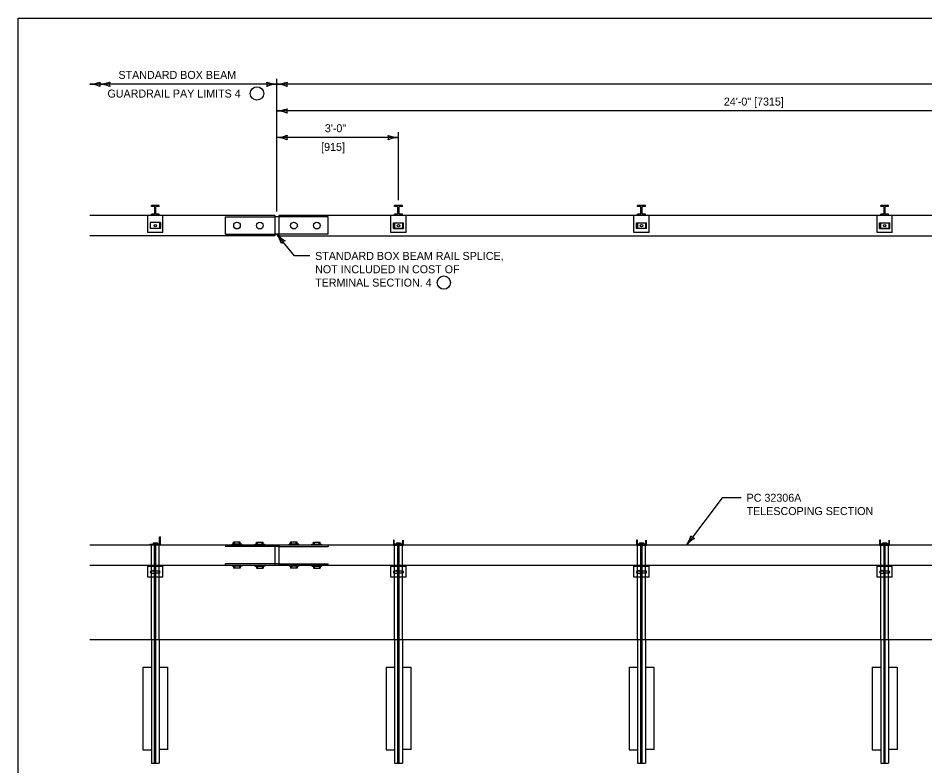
# Model space of a CAD drawing. Extents: x 49991.4 to 50021, y 49987.6 to 50011.4.
# Drawn here: x 49999.38 to 50006.18, y 49993.39 to 49999 of the extents above; entities that cross this region are included whole.
import ezdxf

# ---------------------------------------------------------------- set-up
doc = ezdxf.new("R2010")
doc.units = 0
for name, color, linetype in [('Level 1', 7, 'Continuous'), ('Level 2', 7, 'Continuous'), ('Level 3', 7, 'Continuous'), ('Level 4', 7, 'Continuous')]:
    doc.layers.add(name, color=color, linetype=linetype)

msp = doc.modelspace()

# ---------------------------------------------------------------- linework, layer by layer
at = {"layer": 'Level 1'}
for p, q in [((50000.3826, 49997.5847), (50000.3826, 49997.5939)), ((50000.4416, 49997.5939), (50000.3826, 49997.5939)), ((50000.4075, 49997.5847), (50000.3826, 49997.5847)), ((50000.4075, 49997.5271), (50000.4075, 49997.5847)), ((50000.4167, 49997.5271), (50000.4167, 49997.5847)), ((50000.4416, 49997.5847), (50000.4167, 49997.5847)), ((50000.4416, 49997.5847), (50000.4416, 49997.5939)), ((50002.2056, 49997.5847), (50002.2056, 49997.5939)), ((50002.2647, 49997.5939), (50002.2056, 49997.5939)), ((50002.2306, 49997.5847), (50002.2056, 49997.5847)), ((50002.2306, 49997.5271), (50002.2306, 49997.5847)), ((50002.2397, 49997.5271), (50002.2397, 49997.5847)), ((50002.2647, 49997.5847), (50002.2397, 49997.5847)), ((50002.2647, 49997.5847), (50002.2647, 49997.5939)), ((50004.0288, 49997.5846), (50004.0288, 49997.5938)), ((50004.0879, 49997.5938), (50004.0288, 49997.5938)), ((50004.0539, 49997.5846), (50004.0288, 49997.5846)), ((50004.0539, 49997.527), (50004.0539, 49997.5846)), ((50004.0628, 49997.527), (50004.0628, 49997.5846)), ((50004.0879, 49997.5846), (50004.0628, 49997.5846)), ((50004.0879, 49997.5846), (50004.0879, 49997.5938)), ((50005.8519, 49997.5846), (50005.8519, 49997.5938)), ((50005.911, 49997.5938), (50005.8519, 49997.5938)), ((50005.8769, 49997.5846), (50005.8519, 49997.5846)), ((50005.8769, 49997.527), (50005.8769, 49997.5846)), ((50005.886, 49997.527), (50005.886, 49997.5846)), ((50005.911, 49997.5846), (50005.886, 49997.5846)), ((50005.911, 49997.5846), (50005.911, 49997.5938)), ((50001.3096, 49997.5179), (49999.9212, 49997.5179)), ((50000.4075, 49997.5271), (50000.3826, 49997.5271)), ((50000.3826, 49997.5179), (50000.3826, 49997.5271)), ((50000.4416, 49997.5271), (50000.4167, 49997.5271)), ((50000.4416, 49997.5179), (50000.4416, 49997.5271)), ((50001.3096, 49997.5178), (50001.3096, 49997.366)), ((50001.3379, 49997.5066), (50001.3096, 49997.5066)), ((50001.3379, 49997.5178), (50001.3379, 49997.3659)), ((50008.3123, 49997.5178), (50001.3379, 49997.5178)), ((50002.2306, 49997.5271), (50002.2056, 49997.5271)), ((50002.2056, 49997.5178), (50002.2056, 49997.5271)), ((50002.2647, 49997.5271), (50002.2397, 49997.5271)), ((50002.2647, 49997.5178), (50002.2647, 49997.5271)), ((50004.0539, 49997.527), (50004.0288, 49997.527)), ((50004.0288, 49997.5178), (50004.0288, 49997.527)), ((50004.0879, 49997.527), (50004.0628, 49997.527)), ((50004.0879, 49997.5178), (50004.0879, 49997.527)), ((50005.8769, 49997.527), (50005.8519, 49997.527)), ((50005.8519, 49997.5178), (50005.8519, 49997.527)), ((50005.911, 49997.527), (50005.886, 49997.527)), ((50005.911, 49997.5178), (50005.911, 49997.527)), ((50000.3743, 49997.4642), (50000.3743, 49997.4198)), ((50000.4501, 49997.4642), (50000.3743, 49997.4642)), ((50000.444, 49997.4642), (50000.444, 49997.4198)), ((50000.4501, 49997.4642), (50000.4501, 49997.4198)), ((50002.1978, 49997.4637), (50002.273, 49997.4637)), ((50002.1978, 49997.4203), (50002.1978, 49997.4637)), ((50002.2046, 49997.4637), (50002.2046, 49997.4203)), ((50002.2662, 49997.4637), (50002.2662, 49997.4203)), ((50002.273, 49997.4203), (50002.273, 49997.4637)), ((50002.273, 49997.4203), (50002.273, 49997.4637)), ((50004.0207, 49997.4636), (50004.0959, 49997.4636)), ((50004.0207, 49997.4202), (50004.0207, 49997.4636)), ((50004.0275, 49997.4636), (50004.0275, 49997.4202)), ((50004.0891, 49997.4636), (50004.0891, 49997.4202)), ((50004.0959, 49997.4202), (50004.0959, 49997.4636)), ((50005.8439, 49997.4636), (50005.9192, 49997.4636)), ((50005.8439, 49997.4202), (50005.8439, 49997.4636)), ((50005.8508, 49997.4636), (50005.8508, 49997.4202)), ((50005.9123, 49997.4636), (50005.9123, 49997.4202)), ((50005.9192, 49997.4202), (50005.9192, 49997.4636)), ((50005.9192, 49997.4202), (50005.9192, 49997.4636)), ((50001.3096, 49997.366), (49999.9212, 49997.366)), ((50000.4501, 49997.4198), (50000.3743, 49997.4198)), ((50001.3379, 49997.3771), (50001.3096, 49997.3772)), ((50002.1978, 49997.4203), (50002.273, 49997.4203)), ((50002.273, 49997.4203), (50002.1978, 49997.4203)), ((50004.0959, 49997.4202), (50004.0207, 49997.4202)), ((50005.8439, 49997.4202), (50005.9192, 49997.4202)), ((50005.9192, 49997.4202), (50005.8439, 49997.4202)), ((50008.3121, 49995.0439), (49999.9212, 49995.0439)), ((50000.374, 49995.0439), (50000.374, 49995.0502)), ((50000.374, 49995.0502), (50000.4436, 49995.0502)), ((50000.3964, 49995.0614), (50000.4277, 49995.0614)), ((50000.3964, 49995.0614), (50000.3964, 49995.0502)), ((50000.4033, 49995.0614), (50000.4033, 49995.0502)), ((50000.4211, 49995.0614), (50000.4211, 49995.0502)), ((50000.4277, 49995.0614), (50000.4277, 49995.0502)), ((50000.4436, 49995.1072), (50000.4499, 49995.1072)), ((50000.4436, 49995.0502), (50000.4436, 49995.1072)), ((50000.4499, 49995.0439), (50000.4499, 49995.1072)), ((50001.0599, 49995.0511), (50000.9889, 49995.0511)), ((50000.9889, 49995.044), (50000.9889, 49995.0511)), ((50000.9996, 49995.0511), (50000.9996, 49995.0653)), ((50001.0494, 49995.0653), (50000.9996, 49995.0653)), ((50001.0066, 49995.0511), (50001.0066, 49995.0653)), ((50001.0423, 49995.0511), (50001.0423, 49995.0653)), ((50001.0494, 49995.0511), (50001.0494, 49995.0653)), ((50001.0599, 49995.044), (50001.0599, 49995.0511)), ((50001.1597, 49995.0511), (50001.2308, 49995.0511)), ((50001.1597, 49995.044), (50001.1597, 49995.0511)), ((50001.1704, 49995.0653), (50001.2203, 49995.0653)), ((50001.1704, 49995.0511), (50001.1704, 49995.0653)), ((50001.1775, 49995.0511), (50001.1775, 49995.0653)), ((50001.2132, 49995.0511), (50001.2132, 49995.0653)), ((50001.2203, 49995.0511), (50001.2203, 49995.0653)), ((50001.2308, 49995.044), (50001.2308, 49995.0511)), ((50001.3093, 49995.0439), (50001.3093, 49994.892)), ((50001.3376, 49995.0439), (50001.3376, 49994.892)), ((50001.4873, 49995.0511), (50001.4161, 49995.0511)), ((50001.4161, 49995.044), (50001.4161, 49995.0511)), ((50001.4767, 49995.0653), (50001.4268, 49995.0653)), ((50001.4268, 49995.0511), (50001.4268, 49995.0653)), ((50001.4339, 49995.0511), (50001.4339, 49995.0653)), ((50001.4696, 49995.0511), (50001.4696, 49995.0653)), ((50001.4767, 49995.0511), (50001.4767, 49995.0653)), ((50001.4873, 49995.044), (50001.4873, 49995.0511)), ((50001.5871, 49995.0511), (50001.6582, 49995.0511)), ((50001.5871, 49995.044), (50001.5871, 49995.0511)), ((50001.5977, 49995.0653), (50001.6477, 49995.0653)), ((50001.5977, 49995.0511), (50001.5977, 49995.0653)), ((50001.6048, 49995.0511), (50001.6048, 49995.0653)), ((50001.6405, 49995.0511), (50001.6405, 49995.0653)), ((50001.6477, 49995.0511), (50001.6477, 49995.0653)), ((50001.6582, 49995.044), (50001.6582, 49995.0511)), ((50002.204, 49995.0815), (50002.1971, 49995.0815)), ((50002.1971, 49995.0815), (50002.1971, 49995.0439)), ((50002.1971, 49995.0439), (50002.2724, 49995.0439)), ((50002.204, 49995.0504), (50002.204, 49995.0815)), ((50002.2655, 49995.0504), (50002.204, 49995.0504)), ((50002.2196, 49995.0614), (50002.2509, 49995.0614)), ((50002.2196, 49995.0614), (50002.2196, 49995.0504)), ((50002.2264, 49995.0614), (50002.2264, 49995.0504)), ((50002.2441, 49995.0614), (50002.2441, 49995.0504)), ((50002.2509, 49995.0614), (50002.2509, 49995.0504)), ((50002.2655, 49995.0815), (50002.2655, 49995.0504)), ((50002.2724, 49995.0439), (50002.2724, 49995.0815)), ((50004.0274, 49995.0815), (50004.0205, 49995.0815)), ((50004.0205, 49995.0815), (50004.0205, 49995.0439)), ((50004.0205, 49995.0439), (50004.0958, 49995.0439)), ((50004.0274, 49995.0504), (50004.0274, 49995.0815)), ((50004.0889, 49995.0504), (50004.0274, 49995.0504)), ((50004.0426, 49995.0614), (50004.074, 49995.0614)), ((50004.0426, 49995.0614), (50004.0426, 49995.0504)), ((50004.0495, 49995.0614), (50004.0495, 49995.0504)), ((50004.0673, 49995.0614), (50004.0673, 49995.0504)), ((50004.074, 49995.0614), (50004.074, 49995.0504)), ((50004.0889, 49995.0815), (50004.0889, 49995.0504)), ((50004.0958, 49995.0439), (50004.0958, 49995.0815)), ((50005.8503, 49995.0815), (50005.8435, 49995.0815)), ((50005.8435, 49995.0815), (50005.8435, 49995.0439)), ((50005.8435, 49995.0439), (50005.9187, 49995.0439)), ((50005.8503, 49995.0504), (50005.8503, 49995.0815)), ((50005.9119, 49995.0504), (50005.8503, 49995.0504)), ((50005.8659, 49995.0614), (50005.8972, 49995.0614)), ((50005.8659, 49995.0614), (50005.8659, 49995.0504)), ((50005.8727, 49995.0614), (50005.8727, 49995.0504)), ((50005.8904, 49995.0614), (50005.8904, 49995.0504)), ((50005.8972, 49995.0614), (50005.8972, 49995.0504)), ((50005.9119, 49995.0815), (50005.9119, 49995.0504)), ((50005.9187, 49995.0439), (50005.9187, 49995.0815)), ((50001.3376, 49995.0327), (50001.3093, 49995.0327)), ((50008.3121, 49994.892), (49999.9212, 49994.892)), ((50000.3551, 49994.8034), (50000.3551, 49994.892)), ((50000.469, 49994.8825), (50000.3551, 49994.8825)), ((50000.4415, 49994.8493), (50000.404, 49994.8493)), ((50000.469, 49994.8034), (50000.469, 49994.892)), ((50000.9889, 49994.892), (50000.9889, 49994.8849)), ((50001.0599, 49994.8849), (50000.9889, 49994.8849)), ((50000.9996, 49994.8849), (50000.9996, 49994.8707)), ((50001.0494, 49994.8707), (50000.9996, 49994.8707)), ((50001.0066, 49994.8849), (50001.0066, 49994.8707)), ((50001.0423, 49994.8849), (50001.0423, 49994.8707)), ((50001.0494, 49994.8849), (50001.0494, 49994.8707)), ((50001.0599, 49994.892), (50001.0599, 49994.8849)), ((50001.1597, 49994.892), (50001.1597, 49994.8849)), ((50001.1597, 49994.8849), (50001.2308, 49994.8849)), ((50001.1704, 49994.8849), (50001.1704, 49994.8707)), ((50001.1704, 49994.8707), (50001.2203, 49994.8707)), ((50001.1775, 49994.8849), (50001.1775, 49994.8707)), ((50001.2132, 49994.8849), (50001.2132, 49994.8707)), ((50001.2203, 49994.8849), (50001.2203, 49994.8707)), ((50001.2308, 49994.892), (50001.2308, 49994.8849)), ((50001.3376, 49994.9032), (50001.3093, 49994.9032)), ((50001.4161, 49994.892), (50001.4161, 49994.8849)), ((50001.4873, 49994.8849), (50001.4161, 49994.8849)), ((50001.4268, 49994.8849), (50001.4268, 49994.8707)), ((50001.4767, 49994.8707), (50001.4268, 49994.8707)), ((50001.4339, 49994.8849), (50001.4339, 49994.8707)), ((50001.4696, 49994.8849), (50001.4696, 49994.8707)), ((50001.4767, 49994.8849), (50001.4767, 49994.8707)), ((50001.4873, 49994.892), (50001.4873, 49994.8849)), ((50001.5871, 49994.892), (50001.5871, 49994.8849)), ((50001.5871, 49994.8849), (50001.6582, 49994.8849)), ((50001.5977, 49994.8849), (50001.5977, 49994.8707)), ((50001.5977, 49994.8707), (50001.6477, 49994.8707)), ((50001.6048, 49994.8849), (50001.6048, 49994.8707)), ((50001.6405, 49994.8849), (50001.6405, 49994.8707)), ((50001.6477, 49994.8849), (50001.6477, 49994.8707)), ((50001.6582, 49994.892), (50001.6582, 49994.8849)), ((50002.1782, 49994.8034), (50002.1782, 49994.892)), ((50002.2922, 49994.8825), (50002.1782, 49994.8825)), ((50002.2647, 49994.8493), (50002.2271, 49994.8493)), ((50002.2922, 49994.8034), (50002.2922, 49994.892)), ((50004.0014, 49994.8034), (50004.0014, 49994.892)), ((50004.1153, 49994.8825), (50004.0014, 49994.8825)), ((50004.0878, 49994.8493), (50004.0501, 49994.8493)), ((50004.1153, 49994.8034), (50004.1153, 49994.892)), ((50005.8245, 49994.8035), (50005.8245, 49994.892)), ((50005.9385, 49994.8825), (50005.8245, 49994.8825)), ((50005.9109, 49994.8493), (50005.8733, 49994.8493)), ((50005.9385, 49994.8035), (50005.9385, 49994.892)), ((50000.469, 49994.8034), (50000.3551, 49994.8034)), ((50000.3825, 49994.335), (50000.3825, 49994.8034)), ((50000.4415, 49994.8335), (50000.4041, 49994.8335)), ((50000.4415, 49994.3349), (50000.4415, 49994.8034)), ((50002.2922, 49994.8034), (50002.1782, 49994.8034)), ((50002.2055, 49994.3349), (50002.2055, 49994.8034)), ((50002.2652, 49994.8335), (50002.2272, 49994.8335)), ((50002.2647, 49994.3349), (50002.2647, 49994.8034)), ((50004.1153, 49994.8034), (50004.0014, 49994.8034)), ((50004.0288, 49994.3349), (50004.0288, 49994.8034)), ((50004.0883, 49994.8335), (50004.0503, 49994.8335)), ((50004.0878, 49994.3349), (50004.0878, 49994.8034)), ((50005.9385, 49994.8035), (50005.8245, 49994.8035)), ((50005.8518, 49994.3349), (50005.8518, 49994.8034)), ((50005.9115, 49994.8335), (50005.8735, 49994.8335)), ((50005.9109, 49994.3349), (50005.9109, 49994.8034)), ((49999.9212, 49994.335), (50016.2933, 49994.335))]:
    msp.add_line(p, q, dxfattribs=at)
for points in [[(49999.3835, 49998.9992), (50016.7501, 49998.9992), (50016.7501, 49987.7988), (49999.3835, 49987.7988)], [(50000.3869, 49994.8522), (50000.3993, 49994.8521), (50000.4054, 49994.8413), (50000.399, 49994.8307), (50000.3867, 49994.8309), (50000.3807, 49994.8416)], [(50002.2102, 49994.8522), (50002.2224, 49994.8521), (50002.2284, 49994.8413), (50002.2223, 49994.8307), (50002.2099, 49994.8309), (50002.2038, 49994.8416)], [(50004.0332, 49994.8522), (50004.0455, 49994.8521), (50004.0516, 49994.8413), (50004.0454, 49994.8307), (50004.033, 49994.8309), (50004.027, 49994.8416)], [(50005.8563, 49994.8522), (50005.8688, 49994.8521), (50005.8747, 49994.8413), (50005.8684, 49994.8307), (50005.8562, 49994.8309), (50005.8501, 49994.8416)]]:
    msp.add_lwpolyline(points, close=True, dxfattribs=at)
msp.add_lwpolyline([(50001.3379, 49997.3659), (50008.3123, 49997.3659)], dxfattribs=at)
for centre, radius in [((50000.4123, 49997.442), 0.00948), ((50001.0247, 49997.4419), 0.0249), ((50001.1956, 49997.4419), 0.0249), ((50001.452, 49997.4419), 0.0249), ((50001.6229, 49997.4419), 0.0249), ((50002.2354, 49997.442), 0.00948), ((50004.0583, 49997.4419), 0.00948), ((50005.8816, 49997.4419), 0.00948), ((50000.3931, 49994.8414), 0.0135), ((50002.2162, 49994.8414), 0.0135), ((50004.0393, 49994.8414), 0.0135), ((50005.8625, 49994.8414), 0.0135)]:
    msp.add_circle(centre, radius, dxfattribs=at)
for centre, radius, start, end in [((50000.382, 49994.8414), 0.00794, 88.73965, 270.47349), ((50000.4415, 49994.8414), 0.0079, 270.00657, 89.99353), ((50002.2051, 49994.8414), 0.00794, 88.99088, 270.27808), ((50002.2652, 49994.8414), 0.00794, 269.72192, 91.00912), ((50004.0282, 49994.8414), 0.00794, 88.99088, 270.27808), ((50004.0883, 49994.8414), 0.00794, 269.72192, 91.00912), ((50005.8514, 49994.8414), 0.00794, 88.99088, 270.27808), ((50005.9115, 49994.8414), 0.00794, 269.72192, 91.00912)]:
    msp.add_arc(centre, radius, start, end, dxfattribs=at)
at = {"layer": 'Level 2'}
for centre in [(50001.1747, 49998.4341), (50002.5759, 49997.0142)]:
    msp.add_circle(centre, 0.05, dxfattribs=at)
at = {"layer": 'Level 3'}
for p, q in [((50001.3238, 49997.5466), (50001.3238, 49998.5428)), ((50001.3238, 49998.5028), (49999.9212, 49998.5028)), ((50015.9211, 49998.5028), (50001.3238, 49998.5028)), ((50008.616, 49998.3028), (50001.3238, 49998.3028)), ((50002.2297, 49998.1028), (50001.3293, 49998.1028)), ((50002.2352, 49997.6339), (50002.2352, 49998.1425)), ((50001.4554, 49997.2143), (50001.3269, 49997.3729)), ((50001.5705, 49997.2143), (50001.4554, 49997.2143)), ((50004.664, 49995.3995), (50004.3952, 49995.0439)), ((50004.8062, 49995.3995), (50004.664, 49995.3995))]:
    msp.add_line(p, q, dxfattribs=at)
for centre, radius, start, end in [((49999.9097, 49998.7355), 0.233, 272.82731, 292.07716), ((49999.9831, 49998.7355), 0.233, 272.82731, 292.07716), ((50000.0494, 49998.5028), 0.0548, 162.13882, 197.86118), ((50000.1229, 49998.5028), 0.0548, 162.13882, 197.86118), ((50001.333, 49998.7249), 0.2223, 247.45601, 267.63952), ((50001.1956, 49998.5028), 0.0548, 342.13882, 17.86118), ((50001.3123, 49998.7355), 0.233, 272.82731, 292.07716), ((50001.452, 49998.5028), 0.0548, 162.13882, 197.86118), ((49999.912, 49998.2807), 0.2223, 67.45601, 87.63952), ((49999.9855, 49998.2807), 0.2223, 67.45601, 87.63952), ((50001.3353, 49998.2701), 0.233, 92.82731, 112.07716), ((50001.3146, 49998.2807), 0.2223, 67.45601, 87.63952), ((50001.3123, 49998.5355), 0.233, 272.82731, 292.07716), ((50001.452, 49998.3028), 0.0548, 162.13882, 197.86118), ((50001.3146, 49998.0807), 0.2223, 67.45601, 87.63952), ((50001.3123, 49998.3358), 0.233, 272.82731, 292.07716), ((50001.3146, 49997.881), 0.2223, 67.45601, 87.63952), ((50001.452, 49998.1031), 0.0548, 162.13882, 197.86118), ((50002.2444, 49998.3247), 0.2223, 247.45601, 267.63952), ((50002.107, 49998.1025), 0.0548, 342.13882, 17.86118), ((50002.2467, 49997.8698), 0.233, 92.82731, 112.07716), ((50001.4973, 49997.5326), 0.233, 221.86066, 241.11051), ((50001.1454, 49997.2444), 0.2223, 16.48936, 36.67287), ((50001.4045, 49997.2776), 0.0548, 111.17217, 146.89453), ((50004.2026, 49995.175), 0.233, 325.7459, 344.99575), ((50004.4725, 49995.1462), 0.0548, 215.05741, 250.77977), ((50004.5669, 49994.9027), 0.2223, 120.3746, 140.55811)]:
    msp.add_arc(centre, radius, start, end, dxfattribs=at)
at = {"layer": 'Level 4'}
for p, q in [((50000.355, 49997.3912), (50000.355, 49997.5179)), ((50000.469, 49997.3912), (50000.469, 49997.5179)), ((50000.9392, 49997.3771), (50000.9392, 49997.5066)), ((50000.9392, 49997.5066), (50001.3096, 49997.5066)), ((50001.7084, 49997.5066), (50001.3379, 49997.5066)), ((50001.7084, 49997.3772), (50001.7084, 49997.5066)), ((50002.1782, 49997.3912), (50002.1782, 49997.5178)), ((50002.2921, 49997.3912), (50002.2921, 49997.5178)), ((50004.0012, 49997.3912), (50004.0012, 49997.5178)), ((50004.1153, 49997.3912), (50004.1153, 49997.5178)), ((50005.8244, 49997.3912), (50005.8244, 49997.5178)), ((50005.9384, 49997.3912), (50005.9384, 49997.5178)), ((50000.469, 49997.3912), (50000.355, 49997.3912)), ((50000.9392, 49997.3771), (50001.3096, 49997.3772)), ((50001.7084, 49997.3772), (50001.3379, 49997.3771)), ((50002.2921, 49997.3912), (50002.1782, 49997.3912)), ((50004.1153, 49997.3912), (50004.0012, 49997.3912)), ((50005.9384, 49997.3912), (50005.8244, 49997.3912)), ((50000.3825, 49994.8034), (50000.3825, 49995.0439)), ((50000.4073, 49993.4071), (50000.4073, 49995.0439)), ((50000.4166, 49993.4071), (50000.4166, 49995.0439)), ((50000.4417, 49994.8521), (50000.4417, 49995.0439)), ((50000.939, 49995.0439), (50000.939, 49995.0327)), ((50001.7082, 49995.0439), (50001.7082, 49995.0327)), ((50002.2056, 49994.8035), (50002.2056, 49995.0439)), ((50002.2305, 49993.4071), (50002.2305, 49995.0439)), ((50002.2396, 49993.4071), (50002.2396, 49995.0439)), ((50002.2648, 49994.8035), (50002.2648, 49995.0439)), ((50004.0288, 49994.8035), (50004.0288, 49995.0439)), ((50004.0538, 49993.4071), (50004.0538, 49995.0439)), ((50004.0628, 49993.4071), (50004.0628, 49995.0439)), ((50004.0879, 49994.8035), (50004.0879, 49995.0439)), ((50005.8518, 49994.8035), (50005.8518, 49995.0439)), ((50005.8768, 49993.4071), (50005.8768, 49995.0439)), ((50005.886, 49993.4071), (50005.886, 49995.0439)), ((50005.9109, 49994.8035), (50005.9109, 49995.0439)), ((50001.3093, 49995.0327), (50000.939, 49995.0327)), ((50001.3376, 49995.0327), (50001.7082, 49995.0327)), ((50000.4417, 49994.8034), (50000.4417, 49994.8733)), ((50001.3093, 49994.9032), (50000.939, 49994.9032)), ((50000.939, 49994.892), (50000.939, 49994.9032)), ((50001.3376, 49994.9032), (50001.7082, 49994.9032)), ((50001.7082, 49994.892), (50001.7082, 49994.9032)), ((50000.3825, 49994.335), (50000.3825, 49993.4071)), ((50000.4414, 49994.3349), (50000.4414, 49993.4071)), ((50002.2055, 49994.3349), (50002.2055, 49993.4071)), ((50002.2646, 49994.3349), (50002.2646, 49993.4071)), ((50004.0287, 49994.3349), (50004.0287, 49993.4071)), ((50004.0878, 49994.3349), (50004.0878, 49993.4071)), ((50005.8518, 49994.3349), (50005.8518, 49993.4071)), ((50005.9109, 49994.3349), (50005.9109, 49993.4071)), ((50000.3191, 49994.1269), (50000.3825, 49994.1269)), ((50000.3191, 49994.1269), (50000.3191, 49993.5084)), ((50000.4414, 49994.1269), (50000.5047, 49994.1269)), ((50000.5047, 49994.1269), (50000.5047, 49993.5084)), ((50002.1423, 49994.1269), (50002.2055, 49994.1269)), ((50002.1423, 49994.1269), (50002.1423, 49993.5084)), ((50002.2646, 49994.1269), (50002.3279, 49994.1269)), ((50002.3279, 49994.1269), (50002.3279, 49993.5084)), ((50003.9654, 49994.1269), (50004.0287, 49994.1269)), ((50003.9654, 49994.1269), (50003.9654, 49993.5084)), ((50004.0878, 49994.1269), (50004.1509, 49994.1269)), ((50004.1509, 49994.1269), (50004.1509, 49993.5084)), ((50005.7885, 49994.1269), (50005.8518, 49994.1269)), ((50005.7885, 49994.1269), (50005.7885, 49993.5084)), ((50005.9109, 49994.1269), (50005.9741, 49994.1269)), ((50005.9741, 49994.1269), (50005.9741, 49993.5084)), ((50000.3191, 49993.5084), (50000.3825, 49993.5084)), ((50000.4414, 49993.5118), (50000.5047, 49993.5118)), ((50002.1423, 49993.5084), (50002.2055, 49993.5084)), ((50002.2646, 49993.5118), (50002.3279, 49993.5118)), ((50003.9654, 49993.5084), (50004.0287, 49993.5084)), ((50004.0878, 49993.5118), (50004.1509, 49993.5118)), ((50005.7885, 49993.5084), (50005.8518, 49993.5084)), ((50005.9109, 49993.5118), (50005.9741, 49993.5118)), ((50000.3825, 49993.4071), (50000.4414, 49993.4071)), ((50002.2055, 49993.4071), (50002.2646, 49993.4071)), ((50004.0287, 49993.4071), (50004.0878, 49993.4071)), ((50005.8518, 49993.4071), (50005.9109, 49993.4071))]:
    msp.add_line(p, q, dxfattribs=at)

# ---------------------------------------------------------------- texts
at = {"layer": 'Level 2'}
for s, p in [('STANDARD BOX BEAM', (50000.1357, 49998.5428)), ('GUARDRAIL PAY LIMITS 4', (50000.0535, 49998.4028)), ('24\'-0" [7315]', (50004.6755, 49998.3428)), ('3\'-0"', (50001.6834, 49998.1428)), ('[915]', (50001.6558, 49998.0028)), ('STANDARD BOX BEAM RAIL SPLICE,', (50001.6105, 49997.1843)), ('NOT INCLUDED IN COST OF', (50001.6105, 49997.0843)), ('TERMINAL SECTION. 4', (50001.6105, 49996.9843)), ('PC 32306A', (50004.8462, 49995.3695)), ('TELESCOPING SECTION', (50004.8462, 49995.2695))]:
    msp.add_text(s, height=0.06, dxfattribs=at).set_placement(p)

doc.saveas('drawing.dxf')
